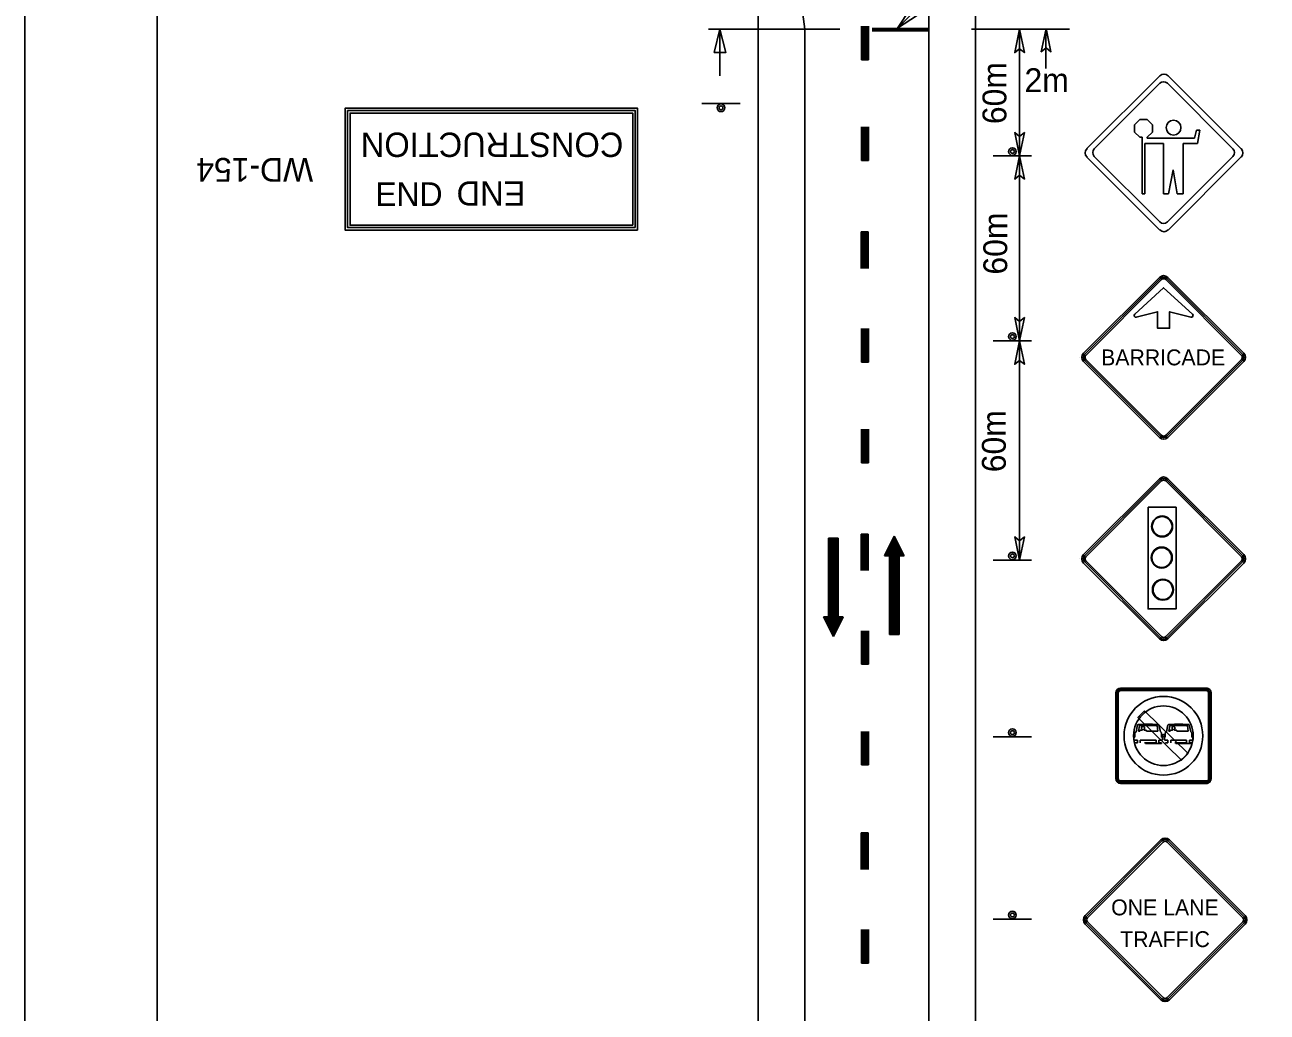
# Model space of a CAD drawing. Extents: x 1062 to 1288, y 239 to 518.
# Drawn here: x 1071.6 to 1165.3, y 299.6 to 374.1 of the extents above; entities that cross this region are included whole.
import ezdxf

# ---------------------------------------------------------------- set-up
doc = ezdxf.new("R2010")
doc.units = 0
for name, color, linetype in [('Level 1', 7, 'Continuous'), ('Level 10', 7, 'Continuous'), ('Level 17', 7, 'Continuous'), ('Level 44', 7, 'Continuous'), ('Level 5', 7, 'Continuous'), ('Level 60', 7, 'Continuous')]:
    doc.layers.add(name, color=color, linetype=linetype)

# ---------------------------------------------------------------- blocks, each defined once
blk = doc.blocks.new('TAH01')
at = {"layer": 'Level 5'}
blk.add_lwpolyline([(0, 0), (-3, -0.62), (-2.504, 0), (-3, 0.62)], close=True, dxfattribs=at)
blk = doc.blocks.new('LT1')
at = {"layer": 'Level 5'}
blk.add_blockref('TAH01', (0, 0), dxfattribs=at)

msp = doc.modelspace()

# ---------------------------------------------------------------- linework, layer by layer
at = {"layer": 'Level 1'}
for p, q in [((1155.736, 366.988), (1155.342, 366.594)), ((1156.293, 366.988), (1155.736, 366.988)), ((1156.687, 366.594), (1156.293, 366.988)), ((1155.342, 366.594), (1155.342, 366.037)), ((1155.342, 366.037), (1155.736, 365.643)), ((1156.293, 365.643), (1156.687, 366.037)), ((1156.687, 366.037), (1156.687, 366.594)), ((1160.007, 366.169), (1159.863, 365.57)), ((1160.257, 366.169), (1160.007, 366.169)), ((1160.094, 365.168), (1160.257, 366.169)), ((1155.736, 365.643), (1155.914, 365.643)), ((1155.914, 365.643), (1155.914, 361.377)), ((1156.11, 361.377), (1156.11, 365.168)), ((1156.11, 365.168), (1157.53, 365.168)), ((1156.293, 365.57), (1156.293, 365.643)), ((1159.863, 365.57), (1156.293, 365.57)), ((1157.53, 365.168), (1157.53, 361.377)), ((1159.018, 361.377), (1159.018, 365.168)), ((1159.018, 365.168), (1160.094, 365.168)), ((1157.906, 361.377), (1158.243, 363.193)), ((1158.243, 363.193), (1158.56, 361.377)), ((1155.914, 361.377), (1156.11, 361.377)), ((1157.53, 361.377), (1157.906, 361.377)), ((1158.56, 361.377), (1159.018, 361.377))]:
    msp.add_line(p, q, dxfattribs=at)
msp.add_circle((1158.279, 366.369), 0.559, dxfattribs=at)
at = {"layer": 'Level 10'}
for p, q in [((1143.326, 249.993), (1143.326, 410.898)), ((1130.442, 373.792), (1126.928, 401.621)), ((1126.928, 250.013), (1126.928, 401.621)), ((1137.44, 373.873), (1145.804, 382.163)), ((1139.812, 250.013), (1139.812, 380.515)), ((1133.081, 373.792), (1123.162, 373.792)), ((1124.041, 370.279), (1124.041, 373.792)), ((1130.442, 249.953), (1130.442, 373.792)), ((1139.812, 373.85), (1135.527, 373.85)), ((1139.812, 373.85), (1135.527, 373.85)), ((1139.812, 373.792), (1135.527, 373.792)), ((1139.812, 373.792), (1135.527, 373.792)), ((1139.812, 373.792), (1135.527, 373.792)), ((1139.812, 373.733), (1135.527, 373.733)), ((1139.812, 373.733), (1135.527, 373.733)), ((1139.812, 373.675), (1135.527, 373.675)), ((1143.036, 373.792), (1150.433, 373.792)), ((1146.654, 364.24), (1146.654, 373.792)), ((1148.627, 373.792), (1148.627, 370.828)), ((1146.654, 350.271), (1146.654, 364.24)), ((1146.654, 333.721), (1146.654, 350.271)), ((1132.227, 329.438), (1132.227, 335.379)), ((1132.969, 335.379), (1132.227, 335.379)), ((1132.227, 328.695), (1132.227, 335.379)), ((1132.32, 328.511), (1132.32, 335.379)), ((1132.414, 328.324), (1132.414, 335.379)), ((1132.506, 328.139), (1132.506, 335.379)), ((1132.598, 327.953), (1132.598, 335.379)), ((1132.691, 328.139), (1132.691, 335.379)), ((1132.785, 328.324), (1132.785, 335.379)), ((1132.877, 328.511), (1132.877, 335.379)), ((1132.969, 329.438), (1132.969, 335.379)), ((1132.969, 328.695), (1132.969, 335.379)), ((1137.2, 335.543), (1136.457, 334.057)), ((1136.922, 334.985), (1136.922, 328.116)), ((1137.012, 335.171), (1137.012, 328.116)), ((1137.108, 335.356), (1137.108, 328.116)), ((1137.2, 335.543), (1137.2, 328.116)), ((1137.2, 335.543), (1137.942, 334.057)), ((1137.292, 335.356), (1137.292, 328.116)), ((1137.385, 335.171), (1137.385, 328.116)), ((1137.478, 334.985), (1137.478, 328.116)), ((1136.457, 334.057), (1136.828, 334.057)), ((1136.55, 334.243), (1136.55, 334.057)), ((1136.642, 334.429), (1136.642, 334.057)), ((1136.735, 334.614), (1136.735, 334.057)), ((1136.828, 334.801), (1136.828, 328.116)), ((1136.828, 334.057), (1136.828, 328.116)), ((1137.57, 334.801), (1137.57, 328.116)), ((1137.57, 334.057), (1137.57, 328.116)), ((1137.57, 334.057), (1137.942, 334.057)), ((1137.664, 334.614), (1137.664, 334.057)), ((1137.757, 334.429), (1137.757, 334.057)), ((1137.85, 334.243), (1137.85, 334.057)), ((1132.598, 327.953), (1131.856, 329.438)), ((1132.227, 329.438), (1131.856, 329.438)), ((1131.949, 329.253), (1131.949, 329.438)), ((1132.042, 329.066), (1132.042, 329.438)), ((1132.134, 328.881), (1132.134, 329.438)), ((1132.598, 327.953), (1133.341, 329.438)), ((1133.341, 329.438), (1132.969, 329.438)), ((1133.064, 328.881), (1133.064, 329.438)), ((1133.156, 329.066), (1133.156, 329.438)), ((1133.248, 329.253), (1133.248, 329.438)), ((1136.828, 328.116), (1137.57, 328.116))]:
    msp.add_line(p, q, dxfattribs=at)
for points in [[(1123.601, 372.036), (1124.041, 373.792), (1124.48, 372.036)], [(1156.354, 337.71), (1158.47, 337.71), (1158.47, 330.036), (1156.354, 330.036)]]:
    msp.add_lwpolyline(points, close=True, dxfattribs=at)
for centre in [(1157.42, 336.266), (1157.389, 333.917), (1157.477, 331.493)]:
    msp.add_circle(centre, 0.745, dxfattribs=at)
at = {"layer": 'Level 17'}
for p, q in [((1117.822, 367.838), (1095.742, 367.838)), ((1151.493, 349.35), (1157.212, 355.069)), ((1151.578, 349.265), (1157.297, 354.985)), ((1151.663, 349.181), (1157.382, 354.9)), ((1157.687, 354.9), (1163.407, 349.181)), ((1157.772, 354.985), (1163.491, 349.265)), ((1157.857, 355.069), (1163.576, 349.35)), ((1155.471, 352.067), (1155.471, 352.067)), ((1155.471, 352.067), (1155.471, 352.067)), ((1155.471, 352.067), (1155.471, 352.067)), ((1151.171, 349.028), (1151.171, 349.028)), ((1157.212, 342.986), (1151.493, 348.705)), ((1157.297, 343.071), (1151.578, 348.79)), ((1157.382, 343.156), (1151.663, 348.875)), ((1163.407, 348.875), (1157.687, 343.156)), ((1163.491, 348.79), (1157.772, 343.071)), ((1163.576, 348.705), (1157.857, 342.986)), ((1151.493, 334.149), (1157.212, 339.868)), ((1151.577, 334.064), (1157.297, 339.783)), ((1151.662, 333.979), (1157.381, 339.698)), ((1157.687, 339.698), (1163.406, 333.979)), ((1157.772, 339.783), (1163.491, 334.064)), ((1157.857, 339.868), (1163.576, 334.149)), ((1151.17, 333.826), (1151.17, 333.826)), ((1157.212, 327.785), (1151.493, 333.504)), ((1157.297, 327.87), (1151.577, 333.589)), ((1157.381, 327.954), (1151.662, 333.673)), ((1163.406, 333.673), (1157.687, 327.954)), ((1163.491, 333.589), (1157.772, 327.87)), ((1163.576, 333.504), (1157.857, 327.785)), ((1153.917, 317.236), (1153.917, 323.7)), ((1154.012, 317.236), (1154.012, 323.7)), ((1154.108, 317.236), (1154.108, 323.7)), ((1154.282, 324.065), (1160.749, 324.069)), ((1154.282, 323.969), (1160.749, 323.973)), ((1154.282, 323.873), (1160.749, 323.877)), ((1160.924, 323.704), (1160.923, 317.232)), ((1161.019, 323.704), (1161.019, 317.232)), ((1161.115, 323.704), (1161.115, 317.232)), ((1155.367, 320.697), (1155.449, 320.754)), ((1155.449, 320.754), (1155.569, 321.299)), ((1155.642, 320.804), (1155.711, 321.222)), ((1155.733, 320.804), (1155.642, 320.804)), ((1155.739, 320.859), (1155.733, 320.804)), ((1155.742, 321.254), (1156.997, 321.254)), ((1155.914, 320.9), (1155.776, 320.891)), ((1155.923, 320.95), (1155.923, 320.909)), ((1156.043, 320.909), (1156.043, 320.95)), ((1156.194, 320.891), (1156.055, 320.9)), ((1156.234, 320.804), (1156.226, 320.859)), ((1157.099, 320.804), (1156.234, 320.804)), ((1157.034, 321.222), (1157.099, 320.804)), ((1157.173, 321.299), (1157.293, 320.754)), ((1157.293, 320.754), (1157.375, 320.697)), ((1157.66, 320.697), (1157.742, 320.754)), ((1157.741, 320.754), (1157.861, 321.299)), ((1157.935, 320.804), (1158.004, 321.222)), ((1158.026, 320.804), (1157.935, 320.804)), ((1158.031, 320.859), (1158.026, 320.804)), ((1158.035, 321.254), (1159.29, 321.254)), ((1158.206, 320.9), (1158.068, 320.891)), ((1158.215, 320.95), (1158.215, 320.909)), ((1158.335, 320.909), (1158.335, 320.95)), ((1158.486, 320.891), (1158.348, 320.9)), ((1158.527, 320.804), (1158.518, 320.859)), ((1159.392, 320.804), (1158.527, 320.804)), ((1159.327, 321.222), (1159.392, 320.804)), ((1159.465, 321.299), (1159.585, 320.754)), ((1159.585, 320.754), (1159.667, 320.697)), ((1155.294, 320.184), (1155.294, 320.325)), ((1155.331, 320.363), (1155.367, 320.363)), ((1155.56, 320.147), (1155.331, 320.147)), ((1155.367, 320.363), (1155.367, 320.697)), ((1155.381, 319.871), (1155.381, 319.93)), ((1155.381, 319.93), (1155.56, 319.93)), ((1155.56, 319.93), (1155.56, 320.147)), ((1155.772, 319.93), (1155.772, 320.147)), ((1155.772, 320.147), (1156.97, 320.147)), ((1156.97, 319.93), (1156.093, 319.93)), ((1157.361, 319.871), (1156.152, 319.871)), ((1156.97, 320.147), (1156.97, 319.93)), ((1157.411, 320.147), (1157.181, 320.147)), ((1157.181, 320.147), (1157.181, 319.93)), ((1157.181, 319.93), (1157.361, 319.93)), ((1157.361, 319.93), (1157.361, 319.871)), ((1157.375, 320.697), (1157.375, 320.363)), ((1157.375, 320.363), (1157.411, 320.363)), ((1157.448, 320.325), (1157.448, 320.184)), ((1157.586, 320.184), (1157.586, 320.325)), ((1157.623, 320.363), (1157.66, 320.363)), ((1157.853, 320.147), (1157.623, 320.147)), ((1157.66, 320.363), (1157.66, 320.697)), ((1157.674, 319.871), (1157.674, 319.93)), ((1157.674, 319.93), (1157.853, 319.93)), ((1157.853, 319.93), (1157.853, 320.147)), ((1158.065, 319.93), (1158.065, 320.147)), ((1158.065, 320.147), (1159.262, 320.147)), ((1159.262, 319.93), (1158.385, 319.93)), ((1159.653, 319.871), (1158.445, 319.871)), ((1159.262, 320.147), (1159.262, 319.93)), ((1159.703, 320.147), (1159.474, 320.147)), ((1159.474, 320.147), (1159.474, 319.93)), ((1159.474, 319.93), (1159.653, 319.93)), ((1159.653, 319.93), (1159.653, 319.871)), ((1159.667, 320.697), (1159.667, 320.363)), ((1159.667, 320.363), (1159.703, 320.363)), ((1159.741, 320.325), (1159.741, 320.184)), ((1160.75, 317.059), (1154.282, 317.063)), ((1153.917, 316.872), (1153.917, 316.872)), ((1153.917, 316.872), (1153.917, 316.872)), ((1160.75, 316.963), (1154.282, 316.967)), ((1160.75, 316.867), (1154.282, 316.871)), ((1151.606, 306.895), (1157.325, 312.614)), ((1151.69, 306.81), (1157.409, 312.529)), ((1151.775, 306.725), (1157.494, 312.444)), ((1157.8, 312.444), (1163.519, 306.725)), ((1157.885, 312.529), (1163.604, 306.81)), ((1157.97, 312.614), (1163.689, 306.895)), ((1151.283, 306.572), (1151.283, 306.572)), ((1157.325, 300.531), (1151.606, 306.25)), ((1157.409, 300.616), (1151.69, 306.335)), ((1157.494, 300.701), (1151.775, 306.42)), ((1163.519, 306.42), (1157.8, 300.701)), ((1163.604, 306.335), (1157.885, 300.616)), ((1163.689, 306.25), (1157.97, 300.531))]:
    msp.add_line(p, q, dxfattribs=at)
for points in [[(1117.822, 358.638), (1095.742, 358.638), (1095.742, 367.838), (1117.822, 367.838)], [(1117.638, 358.822), (1095.926, 358.822), (1095.926, 367.654), (1117.638, 367.654)], [(1117.454, 359.006), (1096.11, 359.006), (1096.11, 367.47), (1117.454, 367.47)], [(1156.099, 322.344), (1159.378, 319.124), (1158.87, 318.615), (1155.591, 321.835)]]:
    msp.add_lwpolyline(points, close=True, dxfattribs=at)
for points in [[(1155.348, 352.301), (1157.535, 354.289), (1159.722, 352.301)], [(1155.348, 352.301), (1157.535, 354.289), (1159.722, 352.301)], [(1155.348, 352.301), (1157.535, 354.289), (1159.722, 352.301)], [(1159.593, 352.067), (1157.986, 352.479), (1157.986, 351.229), (1157.079, 351.229), (1157.079, 352.479), (1155.471, 352.067)], [(1159.593, 352.067), (1157.986, 352.479), (1157.986, 351.229), (1157.079, 351.229), (1157.079, 352.479), (1155.471, 352.067)], [(1159.593, 352.067), (1157.986, 352.479), (1157.986, 351.229), (1157.079, 351.229), (1157.079, 352.479), (1155.471, 352.067)]]:
    msp.add_lwpolyline(points, dxfattribs=at)
for radius in [2.972, 2.249, 0.0868]:
    msp.add_circle((1157.517, 320.468), radius, dxfattribs=at)
for centre, radius, start, end in [((1157.535, 354.747), 0.456, 45, 135), ((1157.535, 354.747), 0.336, 45, 135), ((1157.535, 354.747), 0.216, 45, 135), ((1155.439, 352.197), 0.137, 132.30479, 284.40748), ((1155.439, 352.197), 0.137, 132.30479, 284.40748), ((1155.439, 352.197), 0.137, 132.30479, 284.40748), ((1159.628, 352.197), 0.137, 255.59252, 47.69521), ((1159.628, 352.197), 0.137, 255.59252, 47.69521), ((1159.628, 352.197), 0.137, 255.59252, 47.69521), ((1151.816, 349.028), 0.456, 135, 225), ((1151.816, 349.028), 0.336, 135, 225), ((1151.816, 349.028), 0.216, 135, 225), ((1163.254, 349.028), 0.216, 315, 45), ((1163.254, 349.028), 0.336, 315, 45), ((1163.254, 349.028), 0.456, 315, 45), ((1157.535, 343.309), 0.456, 225, 315), ((1157.535, 343.309), 0.336, 225, 315), ((1157.535, 343.309), 0.216, 225, 315), ((1157.534, 339.545), 0.456, 45, 135), ((1157.534, 339.545), 0.336, 45, 135), ((1157.534, 339.545), 0.216, 45, 135), ((1151.815, 333.826), 0.456, 135, 225), ((1151.815, 333.826), 0.336, 135, 225), ((1151.815, 333.826), 0.216, 135, 225), ((1163.253, 333.826), 0.216, 315, 45), ((1163.253, 333.826), 0.336, 315, 45), ((1163.253, 333.826), 0.456, 315, 45), ((1157.534, 328.107), 0.456, 225, 315), ((1157.534, 328.107), 0.336, 225, 315), ((1157.534, 328.107), 0.216, 225, 315), ((1154.283, 323.7), 0.365, 90.03529, 179.99948), ((1154.283, 323.7), 0.269, 90.03529, 179.99948), ((1154.283, 323.7), 0.173, 90.03529, 179.99948), ((1160.75, 323.704), 0.365, 0, 90.03486), ((1160.75, 323.704), 0.269, 0, 90.03486), ((1160.75, 323.704), 0.173, 0, 90.03486), ((1155.745, 321.216), 0.0358, 90, 170.90972), ((1155.777, 320.854), 0.0358, 93.82218, 171.86989), ((1155.986, 321.059), 0.119, 302.76657, 235.94147), ((1155.913, 320.911), 0.0119, 273.79849, 0), ((1155.913, 320.95), 0.012, 0, 60.10537), ((1156.056, 320.948), 0.012, 119.13929, 180), ((1156.056, 320.911), 0.0119, 180, 266.20151), ((1156.192, 320.854), 0.0358, 8.11866, 86.21836), ((1156.998, 321.216), 0.0358, 9.09028, 90), ((1158.038, 321.216), 0.0358, 90, 170.90972), ((1158.069, 320.854), 0.0358, 93.82218, 171.86989), ((1158.278, 321.059), 0.119, 302.76657, 235.94147), ((1158.205, 320.911), 0.0119, 273.79849, 0), ((1158.205, 320.95), 0.012, 0, 60.10537), ((1158.349, 320.948), 0.012, 119.13929, 180), ((1158.349, 320.911), 0.0119, 180, 266.20151), ((1158.485, 320.854), 0.0358, 8.11866, 86.21836), ((1159.291, 321.216), 0.0358, 9.09028, 90), ((1155.332, 320.326), 0.0358, 90.00001, 180.00001), ((1155.332, 320.183), 0.0358, 180.00001, 270), ((1157.411, 320.326), 0.0358, 359.99999, 89.99999), ((1157.411, 320.183), 0.0358, 270, 359.99999), ((1157.625, 320.326), 0.0358, 90.00001, 180.00001), ((1157.625, 320.183), 0.0358, 180.00001, 270), ((1159.704, 320.326), 0.0358, 359.99999, 89.99999), ((1159.704, 320.183), 0.0358, 270, 359.99999), ((1154.283, 317.236), 0.365, 180, 269.96489), ((1154.283, 317.236), 0.269, 180, 269.96489), ((1154.283, 317.236), 0.173, 180, 269.96489), ((1160.75, 317.232), 0.365, 269.96512, 0), ((1160.75, 317.232), 0.269, 269.96512, 0), ((1160.75, 317.232), 0.173, 269.96512, 0), ((1157.647, 312.291), 0.456, 45, 135), ((1157.647, 312.291), 0.336, 45, 135), ((1157.647, 312.291), 0.216, 45, 135), ((1151.928, 306.572), 0.456, 135, 225), ((1151.928, 306.572), 0.336, 135, 225), ((1151.928, 306.572), 0.216, 135, 225), ((1163.366, 306.572), 0.216, 315, 45), ((1163.366, 306.572), 0.336, 315, 45), ((1163.366, 306.572), 0.456, 315, 45), ((1157.647, 300.853), 0.456, 225, 315), ((1157.647, 300.853), 0.336, 225, 315), ((1157.647, 300.853), 0.216, 225, 315)]:
    msp.add_arc(centre, radius, start, end, dxfattribs=at)
for centre in [(1156.372, 321.3), (1158.664, 321.3)]:
    msp.add_ellipse(centre, major_axis=(-0.8, 0), ratio=0.04642, start_param=3.141593, end_param=6.283185, dxfattribs=at)
at = {"layer": 'Level 44'}
for p, q in [((1135.253, 371.488), (1134.727, 371.488)), ((1157.237, 370.271), (1151.743, 364.785)), ((1152.293, 364.781), (1157.237, 369.719)), ((1157.821, 369.719), (1162.759, 364.781)), ((1163.371, 364.785), (1157.887, 370.271)), ((1122.659, 368.191), (1125.561, 368.191)), ((1135.253, 363.889), (1134.727, 363.889)), ((1144.661, 364.24), (1147.562, 364.24)), ((1151.743, 364.135), (1157.237, 358.643)), ((1151.749, 364.135), (1151.743, 364.135)), ((1157.237, 359.255), (1152.293, 364.195)), ((1162.759, 364.195), (1157.821, 359.255)), ((1157.887, 358.643), (1163.371, 364.135)), ((1134.711, 358.507), (1135.239, 358.507)), ((1144.661, 350.271), (1147.562, 350.271)), ((1135.253, 348.675), (1134.727, 348.675)), ((1135.253, 341.077), (1134.727, 341.077)), ((1134.711, 335.695), (1135.239, 335.695)), ((1144.661, 333.721), (1147.562, 333.721)), ((1135.253, 325.863), (1134.727, 325.863)), ((1144.661, 320.376), (1147.562, 320.376)), ((1135.253, 318.264), (1134.727, 318.264)), ((1134.711, 313.13), (1135.239, 313.13)), ((1144.661, 306.612), (1147.562, 306.612)), ((1135.253, 303.298), (1134.727, 303.298))]:
    msp.add_line(p, q, dxfattribs=at)
for points in [[(1134.727, 374.021), (1134.727, 371.488)], [(1134.815, 374.021), (1134.815, 371.488)], [(1134.902, 374.021), (1134.902, 371.488)], [(1134.991, 374.021), (1134.991, 371.488)], [(1135.078, 374.021), (1135.078, 371.488)], [(1135.166, 374.021), (1135.166, 371.488)], [(1135.253, 374.021), (1135.253, 371.488)], [(1134.727, 366.423), (1134.727, 363.889)], [(1134.815, 366.423), (1134.815, 363.889)], [(1134.902, 366.423), (1134.902, 363.889)], [(1134.991, 366.423), (1134.991, 363.889)], [(1135.078, 366.423), (1135.078, 363.889)], [(1135.166, 366.423), (1135.166, 363.889)], [(1135.253, 366.423), (1135.253, 363.889)], [(1134.711, 355.743), (1134.711, 358.507)], [(1134.8, 355.743), (1134.8, 358.507)], [(1134.888, 355.743), (1134.888, 358.507)], [(1134.975, 355.743), (1134.975, 358.507)], [(1135.063, 355.743), (1135.063, 358.507)], [(1135.151, 355.743), (1135.151, 358.507)], [(1135.239, 355.743), (1135.239, 358.507)], [(1134.727, 351.208), (1134.727, 348.675)], [(1134.815, 351.208), (1134.815, 348.675)], [(1134.902, 351.208), (1134.902, 348.675)], [(1134.991, 351.208), (1134.991, 348.675)], [(1135.078, 351.208), (1135.078, 348.675)], [(1135.166, 351.208), (1135.166, 348.675)], [(1135.253, 351.208), (1135.253, 348.675)], [(1134.727, 343.611), (1134.727, 341.077)], [(1134.815, 343.611), (1134.815, 341.077)], [(1134.902, 343.611), (1134.902, 341.077)], [(1134.991, 343.611), (1134.991, 341.077)], [(1135.078, 343.611), (1135.078, 341.077)], [(1135.166, 343.611), (1135.166, 341.077)], [(1135.253, 343.611), (1135.253, 341.077)], [(1134.711, 332.93), (1134.711, 335.695)], [(1134.8, 332.93), (1134.8, 335.695)], [(1134.888, 332.93), (1134.888, 335.695)], [(1134.975, 332.93), (1134.975, 335.695)], [(1135.063, 332.93), (1135.063, 335.695)], [(1135.151, 332.93), (1135.151, 335.695)], [(1135.239, 332.93), (1135.239, 335.695)], [(1134.727, 328.395), (1134.727, 325.863)], [(1134.815, 328.395), (1134.815, 325.863)], [(1134.902, 328.395), (1134.902, 325.863)], [(1134.991, 328.395), (1134.991, 325.863)], [(1135.078, 328.395), (1135.078, 325.863)], [(1135.166, 328.395), (1135.166, 325.863)], [(1135.253, 328.395), (1135.253, 325.863)], [(1134.727, 320.798), (1134.727, 318.264)], [(1134.815, 320.798), (1134.815, 318.264)], [(1134.902, 320.798), (1134.902, 318.264)], [(1134.991, 320.798), (1134.991, 318.264)], [(1135.078, 320.798), (1135.078, 318.264)], [(1135.166, 320.798), (1135.166, 318.264)], [(1135.253, 320.798), (1135.253, 318.264)], [(1134.711, 310.365), (1134.711, 313.13)], [(1134.8, 310.365), (1134.8, 313.13)], [(1134.888, 310.365), (1134.888, 313.13)], [(1134.975, 310.365), (1134.975, 313.13)], [(1135.063, 310.365), (1135.063, 313.13)], [(1135.151, 310.365), (1135.151, 313.13)], [(1135.239, 310.365), (1135.239, 313.13)], [(1134.727, 305.831), (1134.727, 303.298)], [(1134.815, 305.831), (1134.815, 303.298)], [(1134.902, 305.831), (1134.902, 303.298)], [(1134.991, 305.831), (1134.991, 303.298)], [(1135.078, 305.831), (1135.078, 303.298)], [(1135.166, 305.831), (1135.166, 303.298)], [(1135.253, 305.831), (1135.253, 303.298)]]:
    msp.add_lwpolyline(points, dxfattribs=at)
for centre, radius in [((1124.117, 367.866), 0.29), ((1124.117, 367.866), 0.145), ((1146.118, 364.565), 0.29), ((1146.118, 364.565), 0.145), ((1146.118, 350.596), 0.29), ((1146.118, 350.596), 0.145), ((1157.42, 336.266), 0.792), ((1146.118, 334.045), 0.29), ((1146.118, 334.045), 0.145), ((1157.389, 333.917), 0.792), ((1157.477, 331.493), 0.792), ((1146.118, 320.701), 0.29), ((1146.118, 320.701), 0.145), ((1146.118, 306.937), 0.29), ((1146.118, 306.937), 0.145)]:
    msp.add_circle(centre, radius, dxfattribs=at)
for centre, radius, start, end in [((1157.561, 369.948), 0.459, 45, 135), ((1157.528, 369.427), 0.413, 45, 135), ((1152.072, 364.459), 0.459, 135, 224.99999), ((1152.589, 364.487), 0.413, 135, 224.99999), ((1162.468, 364.487), 0.413, 315, 45), ((1163.049, 364.459), 0.459, 315, 45), ((1157.528, 359.548), 0.413, 225, 315), ((1157.561, 358.971), 0.459, 225, 315)]:
    msp.add_arc(centre, radius, start, end, dxfattribs=at)
at = {"layer": 'Level 60'}
for points in [[(1287.562, 517.932), (1071.562, 517.932), (1071.562, 238.932), (1287.562, 238.932)], [(1268.436, 507.123), (1081.562, 507.123), (1081.562, 249.741), (1268.436, 249.741)]]:
    msp.add_lwpolyline(points, close=True, dxfattribs=at)

# ---------------------------------------------------------------- block references
at = {"layer": 'Level 5', "xscale": 0.5856406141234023, "yscale": 0.5856406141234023}
for p, rotation in [((1137.44, 373.873), -135.25684626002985), ((1146.654, 373.792), 90), ((1148.656, 373.855), 90), ((1146.654, 364.24), -90), ((1146.654, 364.24), 90), ((1146.654, 350.271), -90), ((1146.654, 350.271), 90), ((1146.654, 333.721), -90)]:
    msp.add_blockref('LT1', p, dxfattribs=dict(at, rotation=rotation))

# ---------------------------------------------------------------- texts
at = {"layer": 'Level 10'}
msp.add_text('2m', height=1.8, dxfattribs=at).set_placement((1147.03, 369.052))
msp.add_text('WD-154', height=1.8, rotation=180, dxfattribs=at).set_placement((1093.33, 364.082))
at = {"layer": 'Level 17'}
for s, p in [('CONSTRUCTION', (1116.744, 365.997)), ('END', (1109.35, 362.318))]:
    msp.add_text(s, height=1.84, rotation=179.99999, dxfattribs=at).set_placement(p)
for s, p in [('BARRICADE', (1152.813, 348.428)), ('ONE LANE', (1153.571, 306.913)), ('TRAFFIC', (1154.252, 304.513))]:
    msp.add_text(s, height=1.2, dxfattribs=at).set_placement(p)
at = {"layer": 'Level 44'}
for s, rotation, p in [('60m', 90, (1145.66, 366.635)), ('END', 359.99999, (1098.015, 360.449)), ('60m', 90, (1145.723, 355.277)), ('60m', 90, (1145.614, 340.359))]:
    msp.add_text(s, height=1.8, rotation=rotation, dxfattribs=at).set_placement(p)

doc.saveas('drawing.dxf')
